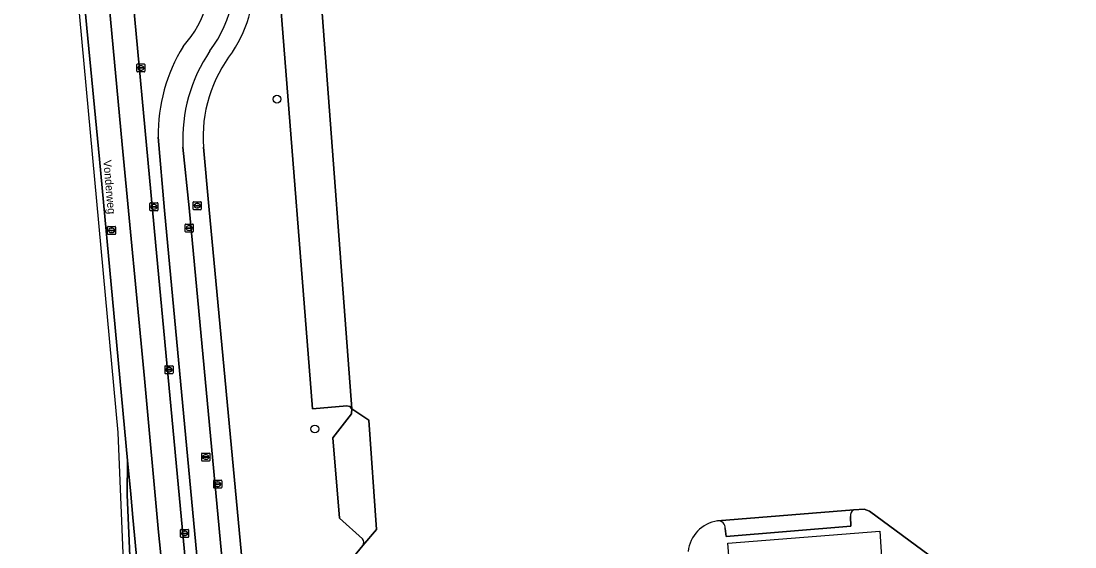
# Model space of a CAD drawing. Extents: x 160675 to 161153, y 383241 to 383714.
# Drawn here: x 160675.3 to 160807, y 383378.1 to 383443.8 of the extents above; entities that cross this region are included whole.
import ezdxf

# ---------------------------------------------------------------- set-up
doc = ezdxf.new("R2010")
doc.units = 0
for name, color, linetype in [('IMGEO_Berm_groen', 7, 'Continuous'), ('IMGEO_Boom', 7, 'Continuous'), ('IMGEO_Erf', 7, 'Continuous'), ('IMGEO_Fietspad_gesloten', 7, 'Continuous'), ('IMGEO_Groenvoorziening', 7, 'Continuous'), ('IMGEO_Hek', 7, 'Continuous'), ('IMGEO_Kolk', 7, 'Continuous'), ('IMGEO_Openbare_ruimte_label', 7, 'Continuous'), ('IMGEO_Parkeervlak_open', 7, 'Continuous'), ('IMGEO_Rijbaan_lokaal_gesloten', 7, 'Continuous'), ('IMGEO_Rioolput', 7, 'Continuous')]:
    doc.layers.add(name, color=color, linetype=linetype)

msp = doc.modelspace()

# ---------------------------------------------------------------- linework, layer by layer
at = {"layer": 'IMGEO_Berm_groen'}
for points in [[(160697.61, 383457.15), (160695.53, 383457.29), (160693.15, 383457.37), (160690.32, 383457.01), (160688.45, 383455.82), (160688.6, 383454.35), (160692.14, 383416.19), (160700.52, 383326.38), (160702.35, 383308.39), (160702.42, 383307.77), (160705.76, 383307.39)], [(160702.06, 383325.99), (160693.25, 383420.12), (160692.44, 383429.3)]]:
    msp.add_lwpolyline(points, dxfattribs=at)
for centre, radius, start, end in [((160686.43, 383449.15), 12.5, 316.976, 14.7951), ((160713.6, 383429.54), 21.16, 148.4252, 180.641)]:
    msp.add_arc(centre, radius, start, end, dxfattribs=at)
at = {"layer": 'IMGEO_Boom'}
for centre in [(160707.3, 383434.03), (160712.03, 383392.85)]:
    msp.add_circle(centre, 0.489, dxfattribs=at)
at = {"layer": 'IMGEO_Erf'}
for points in [[(160712.87, 383445.9), (160716.66, 383395.36), (160718.76, 383393.94), (160719.72, 383380.29), (160718.01, 383378.28), (160715.22, 383374.89), (160718.08, 383337.73), (160724.09, 383332.46)], [(160762.36, 383381.36), (160779.4, 383382.76), (160780.68, 383382.83), (160781.33, 383382.57), (160797.05, 383371.03), (160798.57, 383369.85), (160802.37, 383373.37), (160807.01, 383368.69)]]:
    msp.add_lwpolyline(points, dxfattribs=at)
msp.add_arc((160762.93, 383377.14), 4.26, 97.7114, 174.5244, dxfattribs=at)
at = {"layer": 'IMGEO_Fietspad_gesloten'}
for points in [[(160692.44, 383429.3), (160693.25, 383420.12), (160702.06, 383325.99)], [(160705.03, 383327.48), (160696.31, 383420.48), (160695.54, 383428.02)]]:
    msp.add_lwpolyline(points, dxfattribs=at)
for centre, radius, start, end in [((160686.31, 383449.54), 15.77, 323.008, 14.2898), ((160686.43, 383449.15), 12.5, 316.976, 14.7951), ((160713.6, 383429.54), 21.16, 148.4252, 180.641), ((160715.34, 383428.97), 19.82, 146.0089, 182.7529)]:
    msp.add_arc(centre, radius, start, end, dxfattribs=at)
at = {"layer": 'IMGEO_Groenvoorziening'}
for points in [[(160717.99, 383379.14), (160715.13, 383381.71), (160714.28, 383391.75), (160716.62, 383394.75), (160716.66, 383395.36), (160716.39, 383395.65), (160716.01, 383395.73), (160711.74, 383395.38), (160707.8, 383445.49), (160712.87, 383445.9)], [(160698.1, 383428.04), (160698.78, 383420.67), (160707.33, 383329.61), (160709.82, 383329.75), (160714.62, 383330.06), (160714.65, 383329.67), (160714.99, 383325.82), (160715.73, 383321.08), (160713.43, 383319.24), (160711.34, 383316.61), (160710.16, 383313.94), (160709.85, 383313.25)], [(160718.01, 383378.28), (160719.72, 383380.29), (160718.76, 383393.94), (160716.66, 383395.36), (160716.62, 383394.75), (160714.28, 383391.75), (160715.13, 383381.71), (160717.99, 383379.14)], [(160799.02, 383369.49), (160798.57, 383369.85), (160797.05, 383371.03), (160781.33, 383382.57), (160780.68, 383382.83), (160779.4, 383382.76)], [(160778.95, 383381.92), (160779.02, 383380.73), (160763.44, 383379.43), (160763.31, 383380.43)], [(160715.22, 383374.89), (160718.01, 383378.28)]]:
    msp.add_lwpolyline(points, dxfattribs=at)
for centre, radius, start, end in [((160688.21, 383448.93), 16.25, 326.3214, 5.1534), ((160715.54, 383429.21), 17.48, 142.1962, 183.8175), ((160779.72, 383382.05), 0.782, 114.0525, 189.2157), ((160762.93, 383377.14), 4.26, 97.7114, 174.5244), ((160762.42, 383380.48), 0.891, 357.1695, 93.5628), ((160717.46, 383378.69), 0.693, 323.4414, 39.9004), ((160717.46, 383378.69), 0.693, 323.4414, 39.9004)]:
    msp.add_arc(centre, radius, start, end, dxfattribs=at)
at = {"layer": 'IMGEO_Hek'}
msp.add_lwpolyline([(160714.62, 383330.06), (160733.58, 383331.54), (160748.09, 383332.67), (160751.06, 383333.55), (160755.17, 383335.39), (160766.7, 383340.55), (160766.49, 383343.2), (160763.64, 383378.57), (160782.62, 383380.08), (160783.16, 383371.62), (160791.42, 383362.83), (160798.57, 383369.85)], dxfattribs=at)
at = {"layer": 'IMGEO_Kolk'}
for p, q in [((160689.79, 383437.51), (160689.79, 383438.36)), ((160689.86, 383438.43), (160690.72, 383438.43)), ((160690.05, 383437.93), (160690.05, 383437.94)), ((160690.09, 383437.98), (160690.49, 383437.98)), ((160690.49, 383437.89), (160690.09, 383437.89)), ((160690.28, 383438.21), (160690.3, 383438.21)), ((160690.3, 383437.65), (160690.28, 383437.65)), ((160690.53, 383437.94), (160690.53, 383437.93)), ((160690.79, 383438.36), (160690.79, 383437.51)), ((160690.72, 383437.43), (160689.86, 383437.43)), ((160691.42, 383420.17), (160691.42, 383421.02)), ((160691.49, 383421.1), (160692.35, 383421.1)), ((160691.68, 383420.59), (160691.68, 383420.6)), ((160691.72, 383420.64), (160692.12, 383420.64)), ((160692.12, 383420.55), (160691.72, 383420.55)), ((160691.91, 383420.87), (160691.93, 383420.87)), ((160692.16, 383420.6), (160692.16, 383420.59)), ((160692.42, 383421.02), (160692.42, 383420.17)), ((160692.35, 383420.09), (160691.49, 383420.09)), ((160691.93, 383420.32), (160691.91, 383420.32)), ((160693.31, 383399.83), (160693.31, 383400.68)), ((160693.38, 383400.75), (160694.23, 383400.75)), ((160694.31, 383400.68), (160694.31, 383399.83)), ((160694.23, 383399.75), (160693.38, 383399.75)), ((160693.56, 383400.25), (160693.56, 383400.26)), ((160694, 383400.21), (160693.6, 383400.21)), ((160693.61, 383400.3), (160694, 383400.3)), ((160693.79, 383400.53), (160693.82, 383400.53)), ((160693.82, 383399.97), (160693.79, 383399.97)), ((160694.05, 383400.26), (160694.05, 383400.25)), ((160695.26, 383379.38), (160695.26, 383380.24)), ((160695.33, 383380.31), (160696.19, 383380.31)), ((160695.52, 383379.8), (160695.52, 383379.82)), ((160695.56, 383379.85), (160695.96, 383379.85)), ((160695.96, 383379.77), (160695.56, 383379.77)), ((160695.75, 383380.09), (160695.77, 383380.09)), ((160696, 383379.82), (160696, 383379.8)), ((160696.26, 383380.24), (160696.26, 383379.38)), ((160696.19, 383379.31), (160695.33, 383379.31)), ((160695.77, 383379.53), (160695.75, 383379.53))]:
    msp.add_line(p, q, dxfattribs=at)
for points in [[(160689.79, 383437.51), (160689.79, 383438.36)], [(160689.86, 383438.43), (160690.72, 383438.43)], [(160690.79, 383438.36), (160690.79, 383437.51)], [(160690.72, 383437.43), (160689.86, 383437.43)], [(160691.42, 383420.17), (160691.42, 383421.02)], [(160691.49, 383421.1), (160692.35, 383421.1)], [(160692.42, 383421.02), (160692.42, 383420.17)], [(160692.35, 383420.09), (160691.49, 383420.09)], [(160693.31, 383399.83), (160693.31, 383400.68)], [(160693.38, 383400.75), (160694.23, 383400.75)], [(160694.31, 383400.68), (160694.31, 383399.83)], [(160694.23, 383399.75), (160693.38, 383399.75)], [(160695.26, 383379.38), (160695.26, 383380.24)], [(160695.33, 383380.31), (160696.19, 383380.31)], [(160696.26, 383380.24), (160696.26, 383379.38)], [(160696.19, 383379.31), (160695.33, 383379.31)]]:
    msp.add_lwpolyline(points, dxfattribs=at)
for centre, radius, start, end in [((160689.87, 383438.36), 0.0765, 91.552, 178.448), ((160689.87, 383438.36), 0.0765, 91.552, 178.448), ((160690.09, 383437.94), 0.0403, 85.8775, 175.7526), ((160690.09, 383437.93), 0.0366, 178.938, 274.7102), ((160690.49, 383437.94), 0.0386, 1.7309, 96.639), ((160690.49, 383437.93), 0.043, 264.8664, 352.4533), ((160690.71, 383438.36), 0.0765, 1.552, 88.448), ((160690.71, 383438.36), 0.0765, 1.552, 88.448), ((160689.87, 383437.51), 0.0765, 181.552, 268.448), ((160689.87, 383437.51), 0.0765, 181.552, 268.448), ((160690.71, 383437.51), 0.0765, 271.552, 358.448), ((160690.71, 383437.51), 0.0765, 271.552, 358.448), ((160691.5, 383421.02), 0.0765, 91.552, 178.448), ((160691.5, 383421.02), 0.0765, 91.552, 178.448), ((160691.72, 383420.6), 0.0403, 85.8775, 175.7526), ((160691.72, 383420.59), 0.0366, 178.938, 274.7102), ((160692.12, 383420.6), 0.0386, 1.7309, 96.639), ((160692.12, 383420.59), 0.043, 264.8664, 352.4533), ((160692.34, 383421.02), 0.0765, 1.552, 88.448), ((160692.34, 383421.02), 0.0765, 1.552, 88.448), ((160691.5, 383420.17), 0.0765, 181.552, 268.448), ((160691.5, 383420.17), 0.0765, 181.552, 268.448), ((160692.34, 383420.17), 0.0765, 271.552, 358.448), ((160692.34, 383420.17), 0.0765, 271.552, 358.448), ((160693.38, 383400.68), 0.0765, 91.552, 178.448), ((160693.38, 383400.68), 0.0765, 91.552, 178.448), ((160694.23, 383400.68), 0.0765, 1.552, 88.448), ((160694.23, 383400.68), 0.0765, 1.552, 88.448), ((160693.38, 383399.83), 0.0765, 181.552, 268.448), ((160693.38, 383399.83), 0.0765, 181.552, 268.448), ((160693.6, 383400.26), 0.0403, 85.8775, 175.7526), ((160693.6, 383400.25), 0.0366, 178.938, 274.7102), ((160694.01, 383400.26), 0.0386, 1.7309, 96.639), ((160694.01, 383400.25), 0.043, 264.8664, 352.4533), ((160694.23, 383399.83), 0.0765, 271.552, 358.448), ((160694.23, 383399.83), 0.0765, 271.552, 358.448), ((160695.34, 383380.23), 0.0765, 91.552, 178.448), ((160695.34, 383380.23), 0.0765, 91.552, 178.448), ((160695.56, 383379.81), 0.0403, 85.8775, 175.7526), ((160695.56, 383379.8), 0.0366, 178.938, 274.7102), ((160695.96, 383379.81), 0.0386, 1.7309, 96.639), ((160695.96, 383379.81), 0.043, 264.8664, 352.4533), ((160696.18, 383380.23), 0.0765, 1.552, 88.448), ((160696.18, 383380.23), 0.0765, 1.552, 88.448), ((160695.34, 383379.38), 0.0765, 181.552, 268.448), ((160695.34, 383379.38), 0.0765, 181.552, 268.448), ((160696.18, 383379.38), 0.0765, 271.552, 358.448), ((160696.18, 383379.38), 0.0765, 271.552, 358.448)]:
    msp.add_arc(centre, radius, start, end, dxfattribs=at)
for centre, major_axis, ratio, start_param, end_param in [((160690.28, 383437.93), (-0.387, 0.002), 0.722429, 4.712389, 7.853982), ((160690.3, 383437.93), (-0.39, 0.002), 0.717154, 1.570796, 4.712389), ((160691.91, 383420.59), (-0.387, 0.002), 0.722429, 4.712389, 7.853982), ((160691.93, 383420.59), (-0.39, 0.002), 0.717154, 1.570796, 4.712389), ((160693.79, 383400.25), (-0.387, 0.002), 0.722429, 4.712389, 7.853982), ((160693.82, 383400.25), (-0.39, 0.002), 0.717154, 1.570796, 4.712389), ((160695.75, 383379.81), (-0.387, 0.002), 0.722429, 4.712389, 7.853982), ((160695.77, 383379.81), (-0.39, 0.002), 0.717154, 1.570796, 4.712389)]:
    msp.add_ellipse(centre, major_axis=major_axis, ratio=ratio, start_param=start_param, end_param=end_param, dxfattribs=at)
at = {"layer": 'IMGEO_Parkeervlak_open'}
msp.add_lwpolyline([(160716.66, 383395.36), (160712.87, 383445.9), (160707.8, 383445.49), (160711.74, 383395.38), (160716.01, 383395.73), (160716.39, 383395.65)], close=True, dxfattribs=at)
for points in [[(160779.4, 383382.76), (160762.36, 383381.36)], [(160763.31, 383380.43), (160763.44, 383379.43), (160779.02, 383380.73), (160778.95, 383381.92)]]:
    msp.add_lwpolyline(points, dxfattribs=at)
for centre, radius, start, end in [((160779.72, 383382.05), 0.782, 114.0525, 189.2157), ((160762.42, 383380.48), 0.891, 357.1695, 93.5628)]:
    msp.add_arc(centre, radius, start, end, dxfattribs=at)
at = {"layer": 'IMGEO_Rijbaan_lokaal_gesloten'}
for points in [[(160695.01, 383574.13), (160700.02, 383581.6), (160701.22, 383583.23), (160702.45, 383584.82), (160718.73, 383604.36), (160717.91, 383605.04), (160709.69, 383595.02), (160696.53, 383578.8), (160695.17, 383577.13), (160686.3, 383560.1), (160678.58, 383539.85), (160675.64, 383523.86), (160675.46, 383514.43), (160675.32, 383507.36), (160681.06, 383461.52), (160687.43, 383392.4), (160690.85, 383309.91), (160690.82, 383309.43)], [(160690.82, 383309.43), (160691.54, 383309.35), (160691.49, 383311.74), (160691.1, 383321.26), (160690.84, 383327.37), (160689.89, 383351.36), (160689.11, 383372.17), (160688.6, 383384.62), (160688.61, 383388.91), (160686.9, 383407.32), (160685.13, 383426.54), (160683.55, 383442.89), (160682.06, 383459), (160680.73, 383472.86), (160679.27, 383486.72), (160678.36, 383494.52), (160677.59, 383502.31), (160676.94, 383502.24)], [(160678.19, 383502.38), (160677.59, 383502.31), (160678.36, 383494.52), (160679.27, 383486.72), (160680.73, 383472.86), (160682.06, 383459), (160683.55, 383442.89), (160685.13, 383426.54), (160686.9, 383407.32), (160688.61, 383388.91), (160689.02, 383384.71), (160689.29, 383381.8), (160691.24, 383361.07), (160692.21, 383350.41), (160693.01, 383340.3), (160694.06, 383326.73), (160694.98, 383313.28)], [(160683.4, 383477.16), (160687.97, 383428.37), (160690.74, 383399.13), (160692.5, 383379.97), (160692.9, 383375.91), (160696.66, 383336.41), (160699.23, 383308.29), (160702.42, 383307.77), (160702.35, 383308.39), (160700.52, 383326.38), (160692.14, 383416.19), (160688.6, 383454.35)], [(160695.8, 383312.5), (160696.19, 383308.8), (160699.23, 383308.29), (160696.66, 383336.41), (160692.9, 383375.91), (160692.5, 383379.97), (160690.74, 383399.13), (160687.97, 383428.37), (160683.4, 383477.16)], [(160695.54, 383428.02), (160696.31, 383420.48), (160705.03, 383327.48)], [(160707.39, 383328.91), (160707.33, 383329.61), (160698.78, 383420.67), (160698.1, 383428.04)], [(160688.61, 383388.91), (160688.6, 383384.62), (160689.11, 383372.17), (160689.89, 383351.36), (160690.84, 383327.37), (160691.1, 383321.26), (160691.49, 383311.74), (160691.54, 383309.35), (160694.52, 383309.04), (160694.39, 383312.77)], [(160694.98, 383313.28), (160694.06, 383326.73), (160693.01, 383340.3), (160692.21, 383350.41), (160691.24, 383361.07), (160689.29, 383381.8), (160689.02, 383384.71), (160688.61, 383388.91)]]:
    msp.add_lwpolyline(points, dxfattribs=at)
for centre, radius, start, end in [((160686.31, 383449.54), 15.77, 323.008, 14.2898), ((160688.21, 383448.93), 16.25, 326.3214, 5.1534), ((160715.34, 383428.97), 19.82, 146.0089, 182.7529), ((160715.54, 383429.21), 17.48, 142.1962, 183.8175)]:
    msp.add_arc(centre, radius, start, end, dxfattribs=at)
at = {"layer": 'IMGEO_Rioolput'}
for p, q in [((160696.84, 383420.3), (160696.84, 383421.15)), ((160696.91, 383421.23), (160697.77, 383421.23)), ((160697.1, 383420.72), (160697.1, 383420.73)), ((160697.14, 383420.77), (160697.54, 383420.77)), ((160697.54, 383420.68), (160697.14, 383420.68)), ((160697.35, 383420.45), (160697.32, 383420.45)), ((160697.33, 383421.01), (160697.35, 383421.01)), ((160697.58, 383420.73), (160697.58, 383420.72)), ((160697.84, 383421.15), (160697.84, 383420.3)), ((160697.77, 383420.23), (160696.91, 383420.23)), ((160686.14, 383417.21), (160686.14, 383418.06)), ((160686.21, 383418.14), (160687.06, 383418.14)), ((160686.62, 383417.92), (160686.65, 383417.92)), ((160687.14, 383418.06), (160687.14, 383417.21)), ((160695.83, 383417.5), (160695.83, 383418.36)), ((160695.91, 383418.43), (160696.76, 383418.43)), ((160696.09, 383417.92), (160696.09, 383417.94)), ((160696.13, 383417.97), (160696.53, 383417.97)), ((160696.53, 383417.89), (160696.13, 383417.89)), ((160696.32, 383418.21), (160696.35, 383418.21)), ((160696.58, 383417.94), (160696.58, 383417.92)), ((160696.83, 383418.36), (160696.83, 383417.5)), ((160687.06, 383417.14), (160686.21, 383417.14)), ((160686.39, 383417.63), (160686.39, 383417.64)), ((160686.83, 383417.59), (160686.43, 383417.59)), ((160686.44, 383417.68), (160686.84, 383417.68)), ((160686.65, 383417.36), (160686.62, 383417.36)), ((160686.88, 383417.64), (160686.88, 383417.63)), ((160696.76, 383417.43), (160695.91, 383417.43)), ((160696.34, 383417.65), (160696.32, 383417.65)), ((160697.9, 383388.92), (160697.9, 383389.77)), ((160697.97, 383389.84), (160698.83, 383389.84)), ((160698.83, 383388.84), (160697.97, 383388.84)), ((160698.16, 383389.34), (160698.16, 383389.35)), ((160698.2, 383389.39), (160698.6, 383389.39)), ((160698.59, 383389.3), (160698.2, 383389.3)), ((160698.41, 383389.06), (160698.38, 383389.06)), ((160698.39, 383389.62), (160698.41, 383389.62)), ((160698.64, 383389.35), (160698.64, 383389.34)), ((160698.9, 383389.77), (160698.9, 383388.92)), ((160699.39, 383385.52), (160699.39, 383386.38)), ((160699.46, 383386.45), (160700.32, 383386.45)), ((160699.88, 383386.23), (160699.9, 383386.23)), ((160700.39, 383386.38), (160700.39, 383385.52)), ((160700.32, 383385.45), (160699.46, 383385.45)), ((160699.65, 383385.94), (160699.65, 383385.96)), ((160699.69, 383385.99), (160700.09, 383385.99)), ((160700.08, 383385.91), (160699.69, 383385.91)), ((160699.9, 383385.67), (160699.87, 383385.67)), ((160700.13, 383385.96), (160700.13, 383385.94))]:
    msp.add_line(p, q, dxfattribs=at)
for points in [[(160696.84, 383420.3), (160696.84, 383421.15)], [(160696.91, 383421.23), (160697.77, 383421.23)], [(160697.84, 383421.15), (160697.84, 383420.3)], [(160697.77, 383420.23), (160696.91, 383420.23)], [(160686.14, 383417.21), (160686.14, 383418.06)], [(160686.21, 383418.14), (160687.06, 383418.14)], [(160687.14, 383418.06), (160687.14, 383417.21)], [(160695.83, 383417.5), (160695.83, 383418.36)], [(160695.91, 383418.43), (160696.76, 383418.43)], [(160696.83, 383418.36), (160696.83, 383417.5)], [(160687.06, 383417.14), (160686.21, 383417.14)], [(160696.76, 383417.43), (160695.91, 383417.43)], [(160697.9, 383388.92), (160697.9, 383389.77)], [(160697.97, 383389.84), (160698.83, 383389.84)], [(160698.83, 383388.84), (160697.97, 383388.84)], [(160698.9, 383389.77), (160698.9, 383388.92)], [(160699.39, 383385.52), (160699.39, 383386.38)], [(160699.46, 383386.45), (160700.32, 383386.45)], [(160700.39, 383386.38), (160700.39, 383385.52)], [(160700.32, 383385.45), (160699.46, 383385.45)]]:
    msp.add_lwpolyline(points, dxfattribs=at)
for centre, radius, start, end in [((160696.92, 383421.15), 0.0765, 91.552, 178.448), ((160696.92, 383421.15), 0.0765, 91.552, 178.448), ((160697.14, 383420.73), 0.0403, 85.8775, 175.7526), ((160697.13, 383420.72), 0.0366, 178.938, 274.7102), ((160697.54, 383420.73), 0.0386, 1.7309, 96.639), ((160697.54, 383420.73), 0.043, 264.8664, 352.4533), ((160697.76, 383421.15), 0.0765, 1.552, 88.448), ((160697.76, 383421.15), 0.0765, 1.552, 88.448), ((160696.92, 383420.3), 0.0765, 181.552, 268.448), ((160696.92, 383420.3), 0.0765, 181.552, 268.448), ((160697.76, 383420.3), 0.0765, 271.552, 358.448), ((160697.76, 383420.3), 0.0765, 271.552, 358.448), ((160686.21, 383418.06), 0.0765, 91.552, 178.448), ((160686.21, 383418.06), 0.0765, 91.552, 178.448), ((160687.06, 383418.06), 0.0765, 1.552, 88.448), ((160687.06, 383418.06), 0.0765, 1.552, 88.448), ((160695.91, 383418.35), 0.0765, 91.552, 178.448), ((160695.91, 383418.35), 0.0765, 91.552, 178.448), ((160696.13, 383417.93), 0.0403, 85.8775, 175.7526), ((160696.13, 383417.92), 0.0366, 178.938, 274.7102), ((160696.54, 383417.93), 0.0386, 1.7309, 96.639), ((160696.53, 383417.93), 0.043, 264.8664, 352.4533), ((160696.76, 383418.35), 0.0765, 1.552, 88.448), ((160696.76, 383418.35), 0.0765, 1.552, 88.448), ((160686.21, 383417.21), 0.0765, 181.552, 268.448), ((160686.21, 383417.21), 0.0765, 181.552, 268.448), ((160686.44, 383417.64), 0.0403, 85.8775, 175.7526), ((160686.43, 383417.63), 0.0366, 178.938, 274.7102), ((160686.84, 383417.64), 0.043, 264.8664, 352.4533), ((160686.84, 383417.64), 0.0386, 1.7309, 96.639), ((160687.06, 383417.21), 0.0765, 271.552, 358.448), ((160687.06, 383417.21), 0.0765, 271.552, 358.448), ((160695.91, 383417.5), 0.0765, 181.552, 268.448), ((160695.91, 383417.5), 0.0765, 181.552, 268.448), ((160696.76, 383417.5), 0.0765, 271.552, 358.448), ((160696.76, 383417.5), 0.0765, 271.552, 358.448), ((160697.97, 383389.77), 0.0765, 91.552, 178.448), ((160697.97, 383389.77), 0.0765, 91.552, 178.448), ((160697.97, 383388.92), 0.0765, 181.552, 268.448), ((160697.97, 383388.92), 0.0765, 181.552, 268.448), ((160698.2, 383389.35), 0.0403, 85.8775, 175.7526), ((160698.19, 383389.34), 0.0366, 178.938, 274.7102), ((160698.6, 383389.34), 0.043, 264.8664, 352.4533), ((160698.6, 383389.35), 0.0386, 1.7309, 96.639), ((160698.82, 383389.77), 0.0765, 1.552, 88.448), ((160698.82, 383389.77), 0.0765, 1.552, 88.448), ((160698.82, 383388.92), 0.0765, 271.552, 358.448), ((160698.82, 383388.92), 0.0765, 271.552, 358.448), ((160699.46, 383386.38), 0.0765, 91.552, 178.448), ((160699.46, 383386.38), 0.0765, 91.552, 178.448), ((160700.31, 383386.38), 0.0765, 1.552, 88.448), ((160700.31, 383386.38), 0.0765, 1.552, 88.448), ((160699.46, 383385.53), 0.0765, 181.552, 268.448), ((160699.46, 383385.53), 0.0765, 181.552, 268.448), ((160699.69, 383385.95), 0.0403, 85.8775, 175.7526), ((160699.68, 383385.94), 0.0366, 178.938, 274.7102), ((160700.09, 383385.95), 0.043, 264.8664, 352.4533), ((160700.09, 383385.96), 0.0386, 1.7309, 96.639), ((160700.31, 383385.53), 0.0765, 271.552, 358.448), ((160700.31, 383385.53), 0.0765, 271.552, 358.448)]:
    msp.add_arc(centre, radius, start, end, dxfattribs=at)
for centre, major_axis, ratio, start_param, end_param in [((160697.33, 383420.73), (-0.387, 0.002), 0.722429, 4.712389, 7.853982), ((160697.35, 383420.73), (-0.39, 0.002), 0.717154, 1.570796, 4.712389), ((160686.62, 383417.64), (-0.387, 0.002), 0.722429, 4.712389, 7.853982), ((160686.65, 383417.64), (-0.39, 0.002), 0.717154, 1.570796, 4.712389), ((160696.32, 383417.93), (-0.387, 0.002), 0.722429, 4.712389, 7.853982), ((160696.34, 383417.93), (-0.39, 0.002), 0.717154, 1.570796, 4.712389), ((160698.39, 383389.34), (-0.387, 0.002), 0.722429, 4.712389, 7.853982), ((160698.41, 383389.34), (-0.39, 0.002), 0.717154, 1.570796, 4.712389), ((160699.88, 383385.95), (-0.387, 0.002), 0.722429, 4.712389, 7.853982), ((160699.9, 383385.95), (-0.39, 0.002), 0.717154, 1.570796, 4.712389)]:
    msp.add_ellipse(centre, major_axis=major_axis, ratio=ratio, start_param=start_param, end_param=end_param, dxfattribs=at)

# ---------------------------------------------------------------- texts
at = {"layer": 'IMGEO_Openbare_ruimte_label'}
msp.add_text('Vonderweg', height=1, rotation=274.9921, dxfattribs=at).set_placement((160685.59, 383426.38))

doc.saveas('drawing.dxf')
